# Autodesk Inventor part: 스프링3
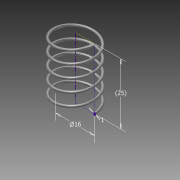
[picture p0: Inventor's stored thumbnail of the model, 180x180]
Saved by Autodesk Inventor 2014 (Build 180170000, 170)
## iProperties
Created: 2015-11
Part Number: 스프링3
Material: 강철, 탄소
Document SubType Name: Modeling
Designer: SEC
Mass: 1.5393 g
Surface Area: 7.90158 cm^2
Volume: 0.195591 cm^3
Density: 7.87 g/cm^3
Appearance: 반연마
Author: SEC
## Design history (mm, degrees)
sketch "스케치1"
  geometry: L1 (0, 0)-(8, 0); L2 (8, 0)-(8, 16.67); L3 (8, 16.67)-(0, 16.67); L4 (0, 16.67)-(0, 0); C1 r 0.5 at (8, 0)
  constraints: 8 end point, 2 parallel, 1 centre point, 1 coincident, 1 horizontal, 1 perpendicular
  dimensions: "d1" = 16 diameter of L2 L4; "d2" = 16.66987 distance of L1.end L2.end (derived); "d3" = 1 diameter of C1
feature "코일1" pitch "d4" = 10; turns "d6" = 5; dims "d5" = 16.66987 (= d2), "d7" = 0, angle "d8" = 90 deg, angle "d9" = 90 deg, "d10" = 0, "d11" = 0
sketch "스케치2"
  geometry: L1 (-8.5, 0)-(-7.5, 0) reference; 1 further point
  constraints: 1 horizontal alignment
extrude "돌출1" cut sketch "스케치2" stored distance "d12" = 10; taper "d13" = 0 deg
node "작업 평면2"
sketch "스케치3"
  geometry: L1 (0.5, 0)-(-0.5, 0) reference; 1 further point
  constraints: 1 horizontal alignment
extrude "돌출2" cut sketch "스케치3" stored distance "d15" = 10; taper "d16" = 0 deg
node "솔리드1"
node "절단 모서리 투영1"
node "절단 모서리 투영2"
other parameters: "d14" = 0
